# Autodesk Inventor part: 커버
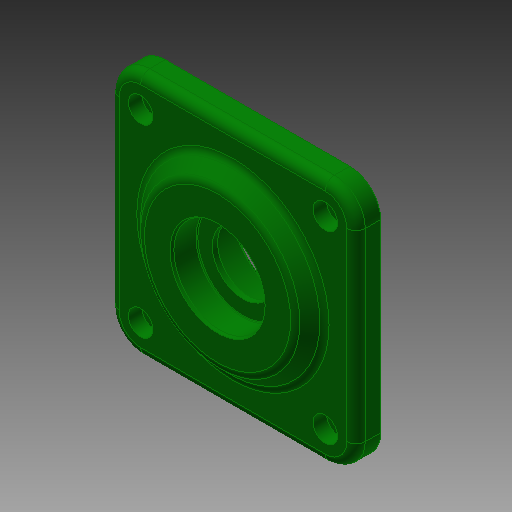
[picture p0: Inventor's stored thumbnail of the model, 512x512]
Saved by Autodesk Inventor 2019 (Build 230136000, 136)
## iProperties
Created: 2016-05
Part Number: 커버
Document SubType Name: Modeling
Designer: mduedu
Density: 2.71 g/cm^3
Material: 알루미늄 6061
Appearance: 진녹색
Author: mduedu
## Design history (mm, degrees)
sketch "스케치1"
  geometry: L1 (-40, -40)-(40, -40); L2 (40, -40)-(40, 40); L3 (40, 40)-(-40, 40); L4 (-40, 40)-(-40, -40); L5 (-40, -40)-(40, 40); L6 (40, -40)-(-40, 40); C1 r 25 at (0, 0); 1 further point
  constraints: 12 end point, 2 midpoint, 2 parallel, 1 centre point, 1 coincident, 1 horizontal, 1 perpendicular
  dimensions: "d30" = 50 diameter of C1; "d33" = 80 distance of L3.end L2.end; "d34" = 80 distance of L2.end L1.end
extrude "돌출1" new body sketch "스케치1" distance "d0" = 8; taper "d1" = 0 deg
fillet "모깎기4" dims "d35" = 10
extrude "돌출2" join sketch "스케치1" distance "d2" = 12; taper "d3" = 0 deg
sketch "스케치2"
  geometry: C1 r 30 at (0, 0); 1 further point
  constraints: 1 centre point, 1 coincident
  dimensions: "d4" = 60 diameter of C1
extrude "돌출3" join sketch "스케치2" distance "d5" = 5; taper "d6" = -45 deg
sketch "스케치3"
  geometry: L1 (30, -40)-(-30, -40) reference; L2 (40, 30)-(40, -30) reference; L3 (-30, 40)-(30, 40) reference; L4 (-40, -30)-(-40, 30) reference; C1 r 30 at (0, 0) reference; A1 r 10 centre (-30, -30) between (-40, -30) and (-30, -40) reference; A2 r 10 centre (30, -30) between (30, -40) and (40, -30) reference; A3 r 10 centre (30, 30) between (40, 30) and (30, 40) reference; A4 r 10 centre (-30, 30) between (-30, 40) and (-40, 30) reference; 4 further points
  constraints: 4 coincident
hole "구멍2" sketch "스케치3" at (-30, 30), (30, 30), (30, -30), (-30, -30) diameter "d36" = 4.5; stored, may be unused: countersink angle "d40" = 90 deg, drill point angle "d42" = 118 deg; dims "d37" = 6, "d38" = 8, "d39" = 4.4, "d41" = 8
fillet "모깎기1" dims "d14" = 3
fillet "모깎기5" dims "d43" = 3
sketch "스케치4"
  geometry: L1 (-23.757, 13)-(23.757, 13) reference; L2 (25, -12)-(-25, -12) reference; L3 (0, -12)-(0, 13); L4 (-20, -12)-(-20, 0); L5 (-20, 0)-(-15, 0); L6 (-15, 0)-(-15, 3); L7 (-15, 3)-(-10, 3); L8 (-10, 3)-(-10, 4.7); L9 (-10, 4.7)-(-15, 4.7); L10 (-15, 4.7)-(-15, 13); 1 further point
  constraints: 16 end point, 6 parallel, 2 midpoint, 2 point on line, 1 perpendicular
  dimensions: "d15" = 40 diameter of L4 L3; "d16" = 30 diameter of L10 L3; "d17" = 8.3 distance of L9.end L10.end; "d18" = 12 distance of L4.start L4.end; "d19" = 3 distance of L5.end L6.end; "d20" = 30 diameter of L6 L3; "d21" = 20 diameter of L8 L3
revolve "회전1" sketch "스케치4" stored, may be unused: angle "d22" = 90 deg
fillet "모깎기2" dims "d23" = 3
fillet "모깎기3" dims "d24" = 0.3
chamfer "모따기1" distance "d25" = 1; stored, may be unused: second distance "d26" = 2, angle "d27" = 45 deg
chamfer "모따기2" distance "d44" = 0.8; stored, may be unused: second distance "d45" = 2, angle "d46" = 30 deg
node "솔리드1"
node "투영된 루프1"
